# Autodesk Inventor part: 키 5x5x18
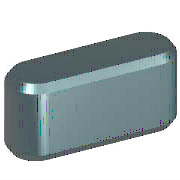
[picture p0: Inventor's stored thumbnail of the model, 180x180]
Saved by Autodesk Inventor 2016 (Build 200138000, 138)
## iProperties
Created: 2012-02
Part Number: 키 5x5x18
Material: 강철, 연강
Description: 키 및 해당 키홈
Document SubType Name: Modeling
Standard: KS B 1311
Designer: mduedu
Standards Organization: KS
Language: ko-KR
Size Designation: 5 x 5 x 18
Categories: <MemberInstance><Categories><Category DisplayName="샤프트 부품" InternalName="7f7aeb1f-a693-4053-b835-cee3144e0d98" Mnemonic="SHFT"><Category DisplayName="키" Interna
Density: 7.86 g/cm^3
Mass: 3.27476 g
Surface Area: 3.57848 cm^2
Volume: 0.416636 cm^3
Appearance: 노란색
IsCustomPart: 1
Author: mduedu
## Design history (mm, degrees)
workplane "Work Plane1"
workplane "Work Plane2"
sketch "스케치1"
  geometry: L1 (2.5, 2.5)-(15.5, 2.5); L2 (15.5, -2.5)-(2.5, -2.5); L3 (0, 9.4)-(0, -7.4) reference; L4 (-5, 0)-(30, 0) reference; L5 (18, 0)-(18, 7); A1 r 2.5 centre (2.5, 0) between (2.5, 2.5) and (2.5, -2.5); A2 r 2.5 centre (15.5, 0) between (15.5, -2.5) and (15.5, 2.5)
  constraints: 6 end point, 5 point on circle, 4 tangent, 3 point on line, 2 centre point, 1 horizontal, 1 parallel, 1 perpendicular
  dimensions: "d0" = 2.5 radius of A1 (= 0.5 x PB); "d13" = 2.5 radius of A2 (= 0.5 x PB); "d14" = 18 distance between parallel lines of L5 L3 (= NLG)
extrude "본체1" new body sketch "스케치1" taper "d3" = 0 deg; stored distance "d4" = 10
workplane "Work Plane3"
body "Solid1"
chamfer "모따기1" distance "d8" = 0.4 (= PHH); stored, may be unused: second distance "d9" = 0.4 (= PHH), angle "d15" = 45 deg
other parameters: "d1" = -3 (= -PNT), "d2" = 2 (= PH - PNT), "NLG" = 18 [user parameter; used in 3 equation terms], "PB" = 5 [user parameter; used in 2 equation terms], "PNT" = 3 [user parameter; used in 2 equation terms], "PH" = 5 [user parameter; used in 1 equation term], "PHH" = 0.4 [user parameter; used in 2 equation terms], "d10" = 0, "d16" = 0, "d17" = 0, "d18" = 0, "WDMIN" = 12 [user parameter], "PLB2" = 18 (= NLG) [user parameter], "WDMAX" = 17 [user parameter], "PLB1" = 18 (= NLG) [user parameter], "RR" = 0.16 [user parameter], "PUEB" = 2.3 [user parameter]
